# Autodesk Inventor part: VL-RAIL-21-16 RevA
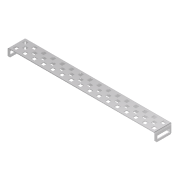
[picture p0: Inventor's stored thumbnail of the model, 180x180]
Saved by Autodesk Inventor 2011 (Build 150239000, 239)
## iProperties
Created: 2007-10
Part Number: VL-RAIL-21-16 RevA
Material: Steel
Document SubType Name: Modeling
Density: 7.85 g/cm^3
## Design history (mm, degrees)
feature "Base1"
workplane "Work Plane1"
workplane "Work Plane2"
workplane "Work Plane3"
workplane "Work Plane4"
workplane "Work Plane5"
workplane "Work Plane6"
sketch "Sketch1" dims "d5" = 25.4
  geometry: L1 (0, 0)-(0, 22.149) reference; L2 (199.238, 0)-(0, 0) reference; L3 (199.238, 22.149)-(199.238, 0) reference; L4 (0, 22.149)-(199.238, 22.149) reference; L5 (179.908, 15.215)-(179.908, 18.821) reference; L6 (180.416, 19.329)-(184.023, 19.329) reference; L7 (184.531, 18.821)-(184.531, 15.215) reference; L8 (184.023, 14.707)-(180.416, 14.707) reference; L9 (184.023, 2.007)-(180.416, 2.007) reference; L10 (179.908, 2.515)-(179.908, 6.121) reference; L11 (180.416, 6.629)-(184.023, 6.629) reference; L12 (184.531, 6.121)-(184.531, 2.515) reference; L13 (190.881, 12.471)-(190.881, 8.865) reference; L14 (190.373, 8.357)-(186.766, 8.357) reference; L15 (186.258, 8.865)-(186.258, 12.471) reference; L16 (186.766, 12.979)-(190.373, 12.979) reference; L17 (197.231, 18.821)-(197.231, 15.215) reference; L18 (196.723, 14.707)-(193.116, 14.707) reference; L19 (192.608, 15.215)-(192.608, 18.821) reference; L20 (193.116, 19.329)-(196.723, 19.329) reference; L21 (197.231, 6.121)-(197.231, 2.515) reference; L22 (196.723, 2.007)-(193.116, 2.007) reference; L23 (192.608, 2.515)-(192.608, 6.121) reference; L24 (193.116, 6.629)-(196.723, 6.629) reference; L25 (173.558, 8.865)-(173.558, 12.471) reference; L26 (174.066, 12.979)-(177.673, 12.979) reference; L27 (178.181, 12.471)-(178.181, 8.865) reference; L28 (177.673, 8.357)-(174.066, 8.357) reference; L29 (171.323, 2.007)-(167.716, 2.007) reference; L30 (167.208, 2.515)-(167.208, 6.121) reference; L31 (167.716, 6.629)-(171.323, 6.629) reference; L32 (171.831, 6.121)-(171.831, 2.515) reference; L33 (158.623, 2.007)-(155.016, 2.007) reference; L34 (154.508, 2.515)-(154.508, 6.121) reference; L35 (155.016, 6.629)-(158.623, 6.629) reference; L36 (159.131, 6.121)-(159.131, 2.515) reference; L37 (145.923, 2.007)-(142.316, 2.007) reference; L38 (141.808, 2.515)-(141.808, 6.121) reference; L39 (142.316, 6.629)-(145.923, 6.629) reference; L40 (146.431, 6.121)-(146.431, 2.515) reference; L41 (133.223, 2.007)-(129.616, 2.007) reference; L42 (129.108, 2.515)-(129.108, 6.121) reference; L43 (129.616, 6.629)-(133.223, 6.629) reference; L44 (133.731, 6.121)-(133.731, 2.515) reference; L45 (120.523, 2.007)-(116.916, 2.007) reference; L46 (116.408, 2.515)-(116.408, 6.121) reference; L47 (116.916, 6.629)-(120.523, 6.629) reference; L48 (121.031, 6.121)-(121.031, 2.515) reference; L49 (107.823, 2.007)-(104.216, 2.007) reference; L50 (103.708, 2.515)-(103.708, 6.121) reference; L51 (104.216, 6.629)-(107.823, 6.629) reference; L52 (108.331, 6.121)-(108.331, 2.515) reference; L53 (95.123, 2.007)-(91.516, 2.007) reference; L54 (91.008, 2.515)-(91.008, 6.121) reference; L55 (91.516, 6.629)-(95.123, 6.629) reference; L56 (95.631, 6.121)-(95.631, 2.515) reference; L57 (82.423, 2.007)-(78.816, 2.007) reference; L58 (78.308, 2.515)-(78.308, 6.121) reference; L59 (78.816, 6.629)-(82.423, 6.629) reference; L60 (82.931, 6.121)-(82.931, 2.515) reference; L61 (69.723, 2.007)-(66.116, 2.007) reference; L62 (65.608, 2.515)-(65.608, 6.121) reference; L63 (66.116, 6.629)-(69.723, 6.629) reference; L64 (70.231, 6.121)-(70.231, 2.515) reference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; C1 r 2.311 at (10.77, 10.668); C2 r 2.311 at (23.47, 10.668); C3 r 2.311 at (36.17, 10.668); C4 r 2.311 at (48.87, 10.668); C5 r 2.311 at (61.57, 10.668); C6 r 2.311 at (74.27, 10.668); C7 r 2.311 at (86.97, 10.668); C8 r 2.311 at (99.67, 10.668); C9 r 2.311 at (112.37, 10.668); C10 r 2.311 at (125.07, 10.668); C11 r 2.311 at (137.77, 10.668); C12 r 2.311 at (150.47, 10.668); C13 r 2.311 at (163.17, 10.668); C14 r 2.311 at (175.87, 10.668); C15 r 2.311 at (188.57, 10.668); A1 r 0.508 centre (180.416, 15.215) between (179.908, 15.215) and (180.416, 14.707) reference; A2 r 0.508 centre (180.416, 18.821) between (180.416, 19.329) and (179.908, 18.821) reference; A3 r 0.508 centre (184.023, 18.821) between (184.531, 18.821) and (184.023, 19.329) reference; A4 r 0.508 centre (184.023, 15.215) between (184.023, 14.707) and (184.531, 15.215) reference; A5 r 0.508 centre (184.023, 2.515) between (184.023, 2.007) and (184.531, 2.515) reference; A6 r 0.508 centre (180.416, 2.515) between (179.908, 2.515) and (180.416, 2.007) reference; A7 r 0.508 centre (180.416, 6.121) between (180.416, 6.629) and (179.908, 6.121) reference; A8 r 0.508 centre (184.023, 6.121) between (184.531, 6.121) and (184.023, 6.629) reference; A9 r 0.508 centre (190.373, 8.865) between (190.373, 8.357) and (190.881, 8.865) reference; A10 r 0.508 centre (186.766, 8.865) between (186.258, 8.865) and (186.766, 8.357) reference; A11 r 0.508 centre (186.766, 12.471) between (186.766, 12.979) and (186.258, 12.471) reference; A12 r 0.508 centre (190.373, 12.471) between (190.881, 12.471) and (190.373, 12.979) reference; A13 r 0.508 centre (196.723, 15.215) between (196.723, 14.707) and (197.231, 15.215) reference; A14 r 0.508 centre (193.116, 15.215) between (192.608, 15.215) and (193.116, 14.707) reference; A15 r 0.508 centre (193.116, 18.821) between (193.116, 19.329) and (192.608, 18.821) reference; A16 r 0.508 centre (196.723, 18.821) between (197.231, 18.821) and (196.723, 19.329) reference; A17 r 0.508 centre (196.723, 2.515) between (196.723, 2.007) and (197.231, 2.515) reference; A18 r 0.508 centre (193.116, 2.515) between (192.608, 2.515) and (193.116, 2.007) reference; A19 r 0.508 centre (193.116, 6.121) between (193.116, 6.629) and (192.608, 6.121) reference; A20 r 0.508 centre (196.723, 6.121) between (197.231, 6.121) and (196.723, 6.629) reference; A21 r 0.508 centre (174.066, 8.865) between (173.558, 8.865) and (174.066, 8.357) reference; A22 r 0.508 centre (174.066, 12.471) between (174.066, 12.979) and (173.558, 12.471) reference; A23 r 0.508 centre (177.673, 12.471) between (178.181, 12.471) and (177.673, 12.979) reference; A24 r 0.508 centre (177.673, 8.865) between (177.673, 8.357) and (178.181, 8.865) reference; A25 r 0.508 centre (167.716, 2.515) between (167.208, 2.515) and (167.716, 2.007) reference; A26 r 0.508 centre (167.716, 6.121) between (167.716, 6.629) and (167.208, 6.121) reference; A27 r 0.508 centre (171.323, 6.121) between (171.831, 6.121) and (171.323, 6.629) reference; A28 r 0.508 centre (171.323, 2.515) between (171.323, 2.007) and (171.831, 2.515) reference; A29 r 0.508 centre (155.016, 2.515) between (154.508, 2.515) and (155.016, 2.007) reference; A30 r 0.508 centre (155.016, 6.121) between (155.016, 6.629) and (154.508, 6.121) reference; A31 r 0.508 centre (158.623, 6.121) between (159.131, 6.121) and (158.623, 6.629) reference; A32 r 0.508 centre (158.623, 2.515) between (158.623, 2.007) and (159.131, 2.515) reference; A33 r 0.508 centre (142.316, 2.515) between (141.808, 2.515) and (142.316, 2.007) reference; A34 r 0.508 centre (142.316, 6.121) between (142.316, 6.629) and (141.808, 6.121) reference; A35 r 0.508 centre (145.923, 6.121) between (146.431, 6.121) and (145.923, 6.629) reference; A36 r 0.508 centre (145.923, 2.515) between (145.923, 2.007) and (146.431, 2.515) reference; A37 r 0.508 centre (129.616, 2.515) between (129.108, 2.515) and (129.616, 2.007) reference; A38 r 0.508 centre (129.616, 6.121) between (129.616, 6.629) and (129.108, 6.121) reference; A39 r 0.508 centre (133.223, 6.121) between (133.731, 6.121) and (133.223, 6.629) reference; A40 r 0.508 centre (133.223, 2.515) between (133.223, 2.007) and (133.731, 2.515) reference; A41 r 0.508 centre (116.916, 2.515) between (116.408, 2.515) and (116.916, 2.007) reference; A42 r 0.508 centre (116.916, 6.121) between (116.916, 6.629) and (116.408, 6.121) reference; A43 r 0.508 centre (120.523, 6.121) between (121.031, 6.121) and (120.523, 6.629) reference; A44 r 0.508 centre (120.523, 2.515) between (120.523, 2.007) and (121.031, 2.515) reference; A45 r 0.508 centre (104.216, 2.515) between (103.708, 2.515) and (104.216, 2.007) reference; A46 r 0.508 centre (104.216, 6.121) between (104.216, 6.629) and (103.708, 6.121) reference; A47 r 0.508 centre (107.823, 6.121) between (108.331, 6.121) and (107.823, 6.629) reference; A48 r 0.508 centre (107.823, 2.515) between (107.823, 2.007) and (108.331, 2.515) reference; A49 r 0.508 centre (91.516, 2.515) between (91.008, 2.515) and (91.516, 2.007) reference; A50 r 0.508 centre (91.516, 6.121) between (91.516, 6.629) and (91.008, 6.121) reference; A51 r 0.508 centre (95.123, 6.121) between (95.631, 6.121) and (95.123, 6.629) reference; A52 r 0.508 centre (95.123, 2.515) between (95.123, 2.007) and (95.631, 2.515) reference; A53 r 0.508 centre (78.816, 2.515) between (78.308, 2.515) and (78.816, 2.007) reference; A54 r 0.508 centre (78.816, 6.121) between (78.816, 6.629) and (78.308, 6.121) reference; A55 r 0.508 centre (82.423, 6.121) between (82.931, 6.121) and (82.423, 6.629) reference; A56 r 0.508 centre (82.423, 2.515) between (82.423, 2.007) and (82.931, 2.515) reference; A57 r 0.508 centre (66.116, 2.515) between (65.608, 2.515) and (66.116, 2.007) reference; A58 r 0.508 centre (66.116, 6.121) between (66.116, 6.629) and (65.608, 6.121) reference; A59 r 0.508 centre (69.723, 6.121) between (70.231, 6.121) and (69.723, 6.629) reference; A60 r 0.508 centre (69.723, 2.515) between (69.723, 2.007) and (70.231, 2.515) reference; A61 r 0.508 centre (53.416, 2.515) between (52.908, 2.515) and (53.416, 2.007) reference; A62 r 0.508 centre (53.416, 6.121) between (53.416, 6.629) and (52.908, 6.121) reference; A63 r 0.508 centre (57.023, 6.121) between (57.531, 6.121) and (57.023, 6.629) reference; A64 r 0.508 centre (57.023, 2.515) between (57.023, 2.007) and (57.531, 2.515) reference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
  constraints: 15 centre point, 3 tangent, 1 horizontal, 28 other
  dimensions: "d2" = 12.7 distance of C1.centre C2.centre
sketch "Sketch2" dims "d12" = 25.4
  geometry: L1 (1.27, -10.719)-(197.968, -10.719) reference; L2 (197.968, -10.719)-(199.238, -9.449) reference; L3 (199.238, -9.449)-(199.238, 0) reference; L4 (0, 0)-(199.238, 0) reference; L5 (0, 0)-(0, -9.449) reference; L6 (0, -9.449)-(1.27, -10.719) reference; L7 (171.831, -3.81)-(171.831, -7.417) reference; L8 (171.323, -7.925)-(167.716, -7.925) reference; L9 (167.208, -7.417)-(167.208, -3.81) reference; L10 (167.716, -3.302)-(171.323, -3.302) reference; L11 (154.508, -7.417)-(154.508, -3.81) reference; L12 (155.016, -3.302)-(158.623, -3.302) reference; L13 (159.131, -3.81)-(159.131, -7.417) reference; L14 (158.623, -7.925)-(155.016, -7.925) reference; L15 (197.231, -3.81)-(197.231, -7.417) reference; L16 (196.723, -7.925)-(180.416, -7.925) reference; L17 (179.908, -7.417)-(179.908, -3.81) reference; L18 (180.416, -3.302)-(196.723, -3.302) reference; L19 (19.329, -7.417)-(19.329, -3.81) reference; L20 (2.515, -7.925)-(18.821, -7.925) reference; L21 (2.007, -3.81)-(2.007, -7.417) reference; L22 (18.821, -3.302)-(2.515, -3.302) reference; L23 (141.808, -7.417)-(141.808, -3.81) reference; L24 (142.316, -3.302)-(145.923, -3.302) reference; L25 (146.431, -3.81)-(146.431, -7.417) reference; L26 (145.923, -7.925)-(142.316, -7.925) reference; L27 (129.108, -7.417)-(129.108, -3.81) reference; L28 (129.616, -3.302)-(133.223, -3.302) reference; L29 (133.731, -3.81)-(133.731, -7.417) reference; L30 (133.223, -7.925)-(129.616, -7.925) reference; L31 (116.408, -7.417)-(116.408, -3.81) reference; L32 (116.916, -3.302)-(120.523, -3.302) reference; L33 (121.031, -3.81)-(121.031, -7.417) reference; L34 (120.523, -7.925)-(116.916, -7.925) reference; L35 (103.708, -7.417)-(103.708, -3.81) reference; L36 (104.216, -3.302)-(107.823, -3.302) reference; L37 (108.331, -3.81)-(108.331, -7.417) reference; L38 (107.823, -7.925)-(104.216, -7.925) reference; L39 (91.008, -7.417)-(91.008, -3.81) reference; L40 (91.516, -3.302)-(95.123, -3.302) reference; L41 (95.631, -3.81)-(95.631, -7.417) reference; L42 (95.123, -7.925)-(91.516, -7.925) reference; L43 (78.308, -7.417)-(78.308, -3.81) reference; L44 (78.816, -3.302)-(82.423, -3.302) reference; L45 (82.931, -3.81)-(82.931, -7.417) reference; L46 (82.423, -7.925)-(78.816, -7.925) reference; L47 (65.608, -7.417)-(65.608, -3.81) reference; L48 (66.116, -3.302)-(69.723, -3.302) reference; L49 (70.231, -3.81)-(70.231, -7.417) reference; L50 (69.723, -7.925)-(66.116, -7.925) reference; L51 (52.908, -7.417)-(52.908, -3.81) reference; L52 (53.416, -3.302)-(57.023, -3.302) reference; L53 (57.531, -3.81)-(57.531, -7.417) reference; L54 (57.023, -7.925)-(53.416, -7.925) reference; L55 (40.208, -7.417)-(40.208, -3.81) reference; L56 (40.716, -3.302)-(44.323, -3.302) reference; L57 (44.831, -3.81)-(44.831, -7.417) reference; L58 (44.323, -7.925)-(40.716, -7.925) reference; L59 (27.508, -7.417)-(27.508, -3.81) reference; L60 (28.016, -3.302)-(31.623, -3.302) reference; L61 (32.131, -3.81)-(32.131, -7.417) reference; L62 (31.623, -7.925)-(28.016, -7.925) reference; C1 r 2.311 at (194.92, -5.613); C2 r 2.311 at (182.22, -5.613); C3 r 2.311 at (169.52, -5.613); C4 r 2.311 at (156.82, -5.613); C5 r 2.311 at (144.12, -5.613); C6 r 2.311 at (131.42, -5.613); C7 r 2.311 at (118.72, -5.613); C8 r 2.311 at (106.02, -5.613); C9 r 2.311 at (93.32, -5.613); C10 r 2.311 at (80.62, -5.613); C11 r 2.311 at (67.92, -5.613); C12 r 2.311 at (55.22, -5.613); C13 r 2.311 at (42.52, -5.613); C14 r 2.311 at (29.82, -5.613); C15 r 2.311 at (17.12, -5.613); C16 r 2.311 at (4.42, -5.613); A1 r 0.508 centre (171.323, -7.417) between (171.323, -7.925) and (171.831, -7.417) reference; A2 r 0.508 centre (167.716, -7.417) between (167.208, -7.417) and (167.716, -7.925) reference; A3 r 0.508 centre (167.716, -3.81) between (167.716, -3.302) and (167.208, -3.81) reference; A4 r 0.508 centre (171.323, -3.81) between (171.831, -3.81) and (171.323, -3.302) reference; A5 r 0.508 centre (155.016, -7.417) between (154.508, -7.417) and (155.016, -7.925) reference; A6 r 0.508 centre (155.016, -3.81) between (155.016, -3.302) and (154.508, -3.81) reference; A7 r 0.508 centre (158.623, -3.81) between (159.131, -3.81) and (158.623, -3.302) reference; A8 r 0.508 centre (158.623, -7.417) between (158.623, -7.925) and (159.131, -7.417) reference; A9 r 0.508 centre (196.723, -7.417) between (196.723, -7.925) and (197.231, -7.417) reference; A10 r 0.508 centre (180.416, -7.417) between (179.908, -7.417) and (180.416, -7.925) reference; A11 r 0.508 centre (180.416, -3.81) between (180.416, -3.302) and (179.908, -3.81) reference; A12 r 0.508 centre (196.723, -3.81) between (197.231, -3.81) and (196.723, -3.302) reference; A13 r 0.508 centre (18.821, -7.417) between (18.821, -7.925) and (19.329, -7.417) reference; A14 r 0.508 centre (2.515, -7.417) between (2.007, -7.417) and (2.515, -7.925) reference; A15 r 0.508 centre (2.515, -3.81) between (2.515, -3.302) and (2.007, -3.81) reference; A16 r 0.508 centre (18.821, -3.81) between (19.329, -3.81) and (18.821, -3.302) reference; A17 r 0.508 centre (142.316, -3.81) between (142.316, -3.302) and (141.808, -3.81) reference; A18 r 0.508 centre (145.923, -3.81) between (146.431, -3.81) and (145.923, -3.302) reference; A19 r 0.508 centre (145.923, -7.417) between (145.923, -7.925) and (146.431, -7.417) reference; A20 r 0.508 centre (142.316, -7.417) between (141.808, -7.417) and (142.316, -7.925) reference; A21 r 0.508 centre (129.616, -3.81) between (129.616, -3.302) and (129.108, -3.81) reference; A22 r 0.508 centre (133.223, -3.81) between (133.731, -3.81) and (133.223, -3.302) reference; A23 r 0.508 centre (133.223, -7.417) between (133.223, -7.925) and (133.731, -7.417) reference; A24 r 0.508 centre (129.616, -7.417) between (129.108, -7.417) and (129.616, -7.925) reference; A25 r 0.508 centre (116.916, -3.81) between (116.916, -3.302) and (116.408, -3.81) reference; A26 r 0.508 centre (120.523, -3.81) between (121.031, -3.81) and (120.523, -3.302) reference; A27 r 0.508 centre (120.523, -7.417) between (120.523, -7.925) and (121.031, -7.417) reference; A28 r 0.508 centre (116.916, -7.417) between (116.408, -7.417) and (116.916, -7.925) reference; A29 r 0.508 centre (104.216, -3.81) between (104.216, -3.302) and (103.708, -3.81) reference; A30 r 0.508 centre (107.823, -3.81) between (108.331, -3.81) and (107.823, -3.302) reference; A31 r 0.508 centre (107.823, -7.417) between (107.823, -7.925) and (108.331, -7.417) reference; A32 r 0.508 centre (104.216, -7.417) between (103.708, -7.417) and (104.216, -7.925) reference; A33 r 0.508 centre (91.516, -3.81) between (91.516, -3.302) and (91.008, -3.81) reference; A34 r 0.508 centre (95.123, -3.81) between (95.631, -3.81) and (95.123, -3.302) reference; A35 r 0.508 centre (95.123, -7.417) between (95.123, -7.925) and (95.631, -7.417) reference; A36 r 0.508 centre (91.516, -7.417) between (91.008, -7.417) and (91.516, -7.925) reference; A37 r 0.508 centre (78.816, -3.81) between (78.816, -3.302) and (78.308, -3.81) reference; A38 r 0.508 centre (82.423, -3.81) between (82.931, -3.81) and (82.423, -3.302) reference; A39 r 0.508 centre (82.423, -7.417) between (82.423, -7.925) and (82.931, -7.417) reference; A40 r 0.508 centre (78.816, -7.417) between (78.308, -7.417) and (78.816, -7.925) reference; A41 r 0.508 centre (66.116, -3.81) between (66.116, -3.302) and (65.608, -3.81) reference; A42 r 0.508 centre (69.723, -3.81) between (70.231, -3.81) and (69.723, -3.302) reference; A43 r 0.508 centre (69.723, -7.417) between (69.723, -7.925) and (70.231, -7.417) reference; A44 r 0.508 centre (66.116, -7.417) between (65.608, -7.417) and (66.116, -7.925) reference; A45 r 0.508 centre (53.416, -3.81) between (53.416, -3.302) and (52.908, -3.81) reference; A46 r 0.508 centre (57.023, -3.81) between (57.531, -3.81) and (57.023, -3.302) reference; A47 r 0.508 centre (57.023, -7.417) between (57.023, -7.925) and (57.531, -7.417) reference; A48 r 0.508 centre (53.416, -7.417) between (52.908, -7.417) and (53.416, -7.925) reference; A49 r 0.508 centre (40.716, -3.81) between (40.716, -3.302) and (40.208, -3.81) reference; A50 r 0.508 centre (44.323, -3.81) between (44.831, -3.81) and (44.323, -3.302) reference; A51 r 0.508 centre (44.323, -7.417) between (44.323, -7.925) and (44.831, -7.417) reference; A52 r 0.508 centre (40.716, -7.417) between (40.208, -7.417) and (40.716, -7.925) reference; A53 r 0.508 centre (28.016, -3.81) between (28.016, -3.302) and (27.508, -3.81) reference; A54 r 0.508 centre (31.623, -3.81) between (32.131, -3.81) and (31.623, -3.302) reference; A55 r 0.508 centre (31.623, -7.417) between (31.623, -7.925) and (32.131, -7.417) reference; A56 r 0.508 centre (28.016, -7.417) between (27.508, -7.417) and (28.016, -7.925) reference
  constraints: 16 centre point, 3 tangent, 1 horizontal, 30 other
  dimensions: "d9" = 12.7 distance of C1.centre C2.centre
sketch "Sketch3"
  geometry: L1 (1.27, -1.27)-(19.863, -1.27) reference; L2 (19.863, -1.27)-(22.149, 1.016) reference; L3 (22.149, 1.016)-(22.149, 9.449) reference; L4 (0, 9.449)-(22.149, 9.449) reference; L5 (0, 9.449)-(0, 0) reference; L6 (0, 0)-(1.27, -1.27) reference; L7 (19.38, 5.639)-(19.38, 2.032) reference; L8 (18.872, 1.524)-(2.565, 1.524) reference; L9 (2.057, 2.032)-(2.057, 5.639) reference; L10 (2.565, 6.147)-(18.872, 6.147) reference; C1 r 2.311 at (4.341, 3.835); C2 r 2.311 at (17.069, 3.835); A1 r 0.508 centre (18.872, 2.032) between (18.872, 1.524) and (19.38, 2.032) reference; A2 r 0.508 centre (2.565, 2.032) between (2.057, 2.032) and (2.565, 1.524) reference; A3 r 0.508 centre (2.565, 5.639) between (2.565, 6.147) and (2.057, 5.639) reference; A4 r 0.508 centre (18.872, 5.639) between (19.38, 5.639) and (18.872, 6.147) reference
  constraints: 5 tangent, 2 centre point
sketch "Sketch4"
  geometry: L1 (-22.149, 1.016)-(-22.149, 9.449) reference; L2 (-22.149, 1.016)-(-19.863, -1.27) reference; L3 (-1.27, -1.27)-(-19.863, -1.27) reference; L4 (-1.27, -1.27)-(0, 0) reference; L5 (0, 9.449)-(0, 0) reference; L6 (-22.149, 9.449)-(0, 9.449) reference; L7 (-2.057, 2.032)-(-2.057, 5.639) reference; L8 (-18.872, 1.524)-(-2.565, 1.524) reference; L9 (-19.38, 5.639)-(-19.38, 2.032) reference; L10 (-2.565, 6.147)-(-18.872, 6.147) reference; C1 r 2.311 at (-4.369, 3.835); C2 r 2.311 at (-17.069, 3.835); A1 r 0.508 centre (-2.565, 2.032) between (-2.565, 1.524) and (-2.057, 2.032) reference; A2 r 0.508 centre (-18.872, 2.032) between (-19.38, 2.032) and (-18.872, 1.524) reference; A3 r 0.508 centre (-18.872, 5.639) between (-18.872, 6.147) and (-19.38, 5.639) reference; A4 r 0.508 centre (-2.565, 5.639) between (-2.057, 5.639) and (-2.565, 6.147) reference
  constraints: 6 tangent, 2 centre point
workplane "Work Plane7"
body "Solid1"
